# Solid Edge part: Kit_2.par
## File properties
Sűrűség: 0,000 kg/m^3
Pontosság: 0,990
Author: bmolnar
Last saved by: bmolnar
Revision: 77
Username: bmolnar
Dokumentum tartalom típus: 0
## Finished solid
Body 1: solid body, 23 faces, 39 edges, 29 vertices.
  Faces by surface: cylinder 10, plane 9, cone 3, torus 1
  Edges by curve: circle 25, line 14
Bounding box of the edges (mm; curved faces can reach further): 55.000 x 54.575 x 5.500, from (-27.5, -25.9, 0.7) to (27.5, 28.675, 6.2).
Cylindrical faces by radius (mm): R1.25 x2, R2.5 x4, R18.5 x1, R23.975 x1, R25.9 x1, R27.5 x1
Conical faces (half-angle, radius in mm at the cone's reference point): 45 deg R18 x1, 45 deg R25.8 x2
Toroidal faces (ring radius, tube radius in mm): R19.3 r0.8 x1
Planar faces by outward normal: +z 2, -z 5, oblique 2
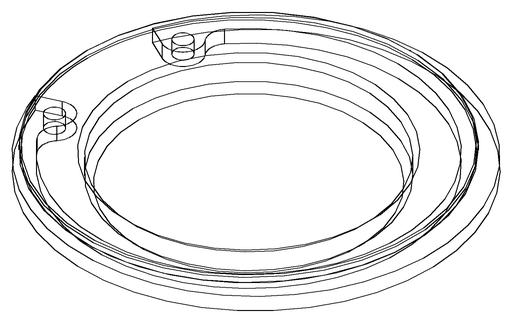
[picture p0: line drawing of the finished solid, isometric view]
